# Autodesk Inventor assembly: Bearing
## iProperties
Created: 2007-11
Part Number: Bearing
Document SubType Name: Assembly
Designer: CM
Mass: 116.125 g
Surface Area: 104.153 cm^2
Volume: 14.7742 cm^3
Density: 7.86 g/cm^3
ClientObjectVersion: 1
Author: CM
